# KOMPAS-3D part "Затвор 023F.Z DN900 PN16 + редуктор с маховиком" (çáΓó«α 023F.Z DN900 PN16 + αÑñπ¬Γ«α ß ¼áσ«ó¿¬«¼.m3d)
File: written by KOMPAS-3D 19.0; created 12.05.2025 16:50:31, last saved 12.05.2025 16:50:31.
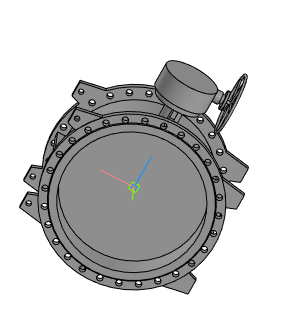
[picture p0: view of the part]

Document properties: Полное имя файла: Затвор 023F.Z DN900 PN16 + редуктор с маховиком.a3d

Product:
- Part/product: Затвор 023F.Z DN900 PN16 + редуктор с маховиком
    Масса: 1063.61

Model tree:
1. Операция без истории:1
